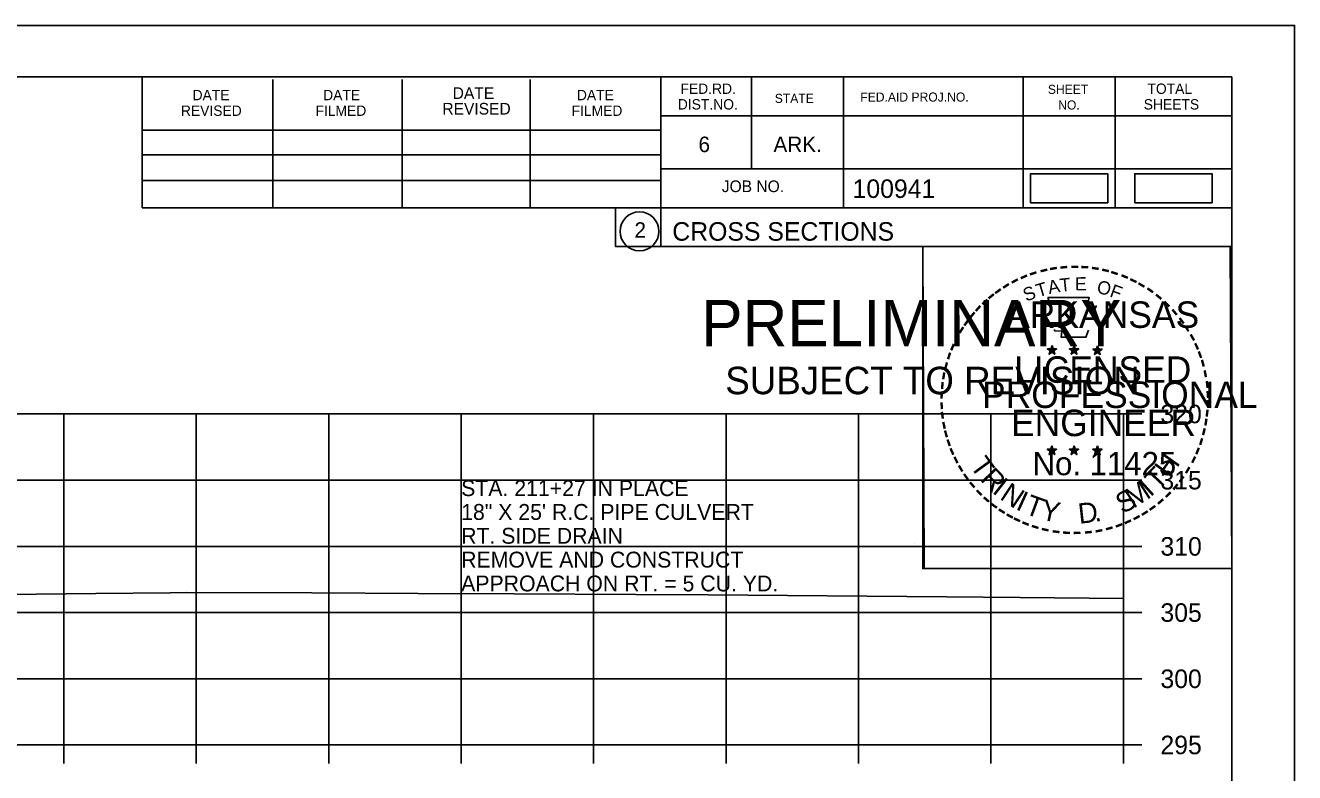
# Model space of a CAD drawing. Extents: x 1370538 to 1372872, y 376220 to 381127.
# Drawn here: x 1370775.7 to 1370871.5, y 379424.9 to 379481.3 of the extents above; entities that cross this region are included whole.
import ezdxf

# ---------------------------------------------------------------- set-up
doc = ezdxf.new("R2010")
doc.units = 0
for name, color, linetype in [('Default', 7, 'Continuous'), ('R_Border Notes', 7, 'Continuous'), ('R_Border PE', 7, 'Continuous'), ('R_Border Prem', 7, 'Continuous'), ('R_Dimension', 7, 'Continuous'), ('R_Grid', 7, 'Continuous'), ('R_No Plot', 7, 'Continuous'), ('R_Water Annot', 7, 'Continuous'), ('T_Indications', 7, 'Continuous'), ('T_Notes', 7, 'Continuous')]:
    doc.layers.add(name, color=color, linetype=linetype)

msp = doc.modelspace()

# ---------------------------------------------------------------- linework, layer by layer
at = {"layer": 'Default'}
for points in [[(1370851.6, 379467.904), (1370857.433, 379467.904), (1370857.433, 379470.09), (1370851.6, 379470.09)], [(1370859.47, 379467.904), (1370865.303, 379467.904), (1370865.303, 379470.09), (1370859.47, 379470.09)]]:
    msp.add_lwpolyline(points, close=True, dxfattribs=at)
at = {"layer": 'R_Border Notes'}
for p, q in [((1370550.607, 379477.407), (1370866.787, 379477.407)), ((1370784.527, 379467.527), (1370784.527, 379477.407)), ((1370794.387, 379467.527), (1370794.387, 379477.207)), ((1370804.147, 379467.527), (1370804.147, 379477.207)), ((1370813.827, 379467.527), (1370813.827, 379477.207)), ((1370823.687, 379477.407), (1370823.687, 379464.607)), ((1370830.527, 379477.407), (1370830.527, 379470.467)), ((1370837.467, 379477.407), (1370837.467, 379467.527)), ((1370851.047, 379477.407), (1370851.047, 379467.527)), ((1370857.987, 379477.407), (1370857.987, 379467.527)), ((1370866.787, 379271.947), (1370866.787, 379477.407)), ((1370866.787, 379474.467), (1370823.687, 379474.467)), ((1370866.787, 379474.487), (1370866.787, 379474.487)), ((1370784.527, 379473.387), (1370823.687, 379473.387)), ((1370784.527, 379471.527), (1370823.687, 379471.527)), ((1370866.787, 379470.467), (1370823.687, 379470.467)), ((1370826.647, 379470.467), (1370866.787, 379470.467)), ((1370784.527, 379467.527), (1370784.527, 379469.587)), ((1370784.527, 379469.587), (1370823.687, 379469.587)), ((1370866.787, 379467.527), (1370784.527, 379467.527)), ((1370823.687, 379464.607), (1370866.787, 379464.607))]:
    msp.add_line(p, q, dxfattribs=at)
msp.add_circle((1370822.073, 379465.743), 1.467, dxfattribs=at)
at = {"layer": 'R_Border Prem'}
for p, q in [((1370858.607, 379426.947), (1370858.607, 379451.947)), ((1370860.007, 379451.947), (1370858.607, 379451.947)), ((1370860.007, 379446.947), (1370858.607, 379446.947)), ((1370860.007, 379441.947), (1370858.607, 379441.947)), ((1370860.007, 379436.947), (1370858.607, 379436.947)), ((1370860.007, 379431.947), (1370858.607, 379431.947)), ((1370558.607, 379426.947), (1370858.607, 379426.947)), ((1370778.607, 379425.547), (1370778.607, 379426.947)), ((1370788.607, 379425.547), (1370788.607, 379426.947)), ((1370798.607, 379425.547), (1370798.607, 379426.947)), ((1370808.607, 379425.547), (1370808.607, 379426.947)), ((1370818.607, 379425.547), (1370818.607, 379426.947)), ((1370828.607, 379425.547), (1370828.607, 379426.947)), ((1370838.607, 379425.547), (1370838.607, 379426.947)), ((1370848.607, 379425.547), (1370848.607, 379426.947)), ((1370858.607, 379425.547), (1370858.607, 379426.947)), ((1370860.007, 379426.947), (1370858.607, 379426.947))]:
    msp.add_line(p, q, dxfattribs=at)
at = {"layer": 'R_Dimension'}
msp.add_lwpolyline([(1370767.559, 379438.24), (1370781.015, 379438.397), (1370786.627, 379438.44), (1370787.849, 379438.47), (1370797.339, 379438.437), (1370805.361, 379438.394), (1370812.609, 379438.367), (1370821.797, 379438.318), (1370827.261, 379438.291), (1370845.258, 379438.14), (1370850.811, 379438.084), (1370858.607, 379438.021)], dxfattribs=at)
at = {"layer": 'R_Grid'}
for p, q in [((1370558.607, 379451.947), (1370858.607, 379451.947)), ((1370778.607, 379426.947), (1370778.607, 379451.947)), ((1370788.607, 379426.947), (1370788.607, 379451.947)), ((1370798.607, 379426.947), (1370798.607, 379451.947)), ((1370808.607, 379426.947), (1370808.607, 379451.947)), ((1370818.607, 379426.947), (1370818.607, 379451.947)), ((1370828.607, 379426.947), (1370828.607, 379451.947)), ((1370838.607, 379426.947), (1370838.607, 379451.947)), ((1370848.607, 379426.947), (1370848.607, 379451.947)), ((1370858.607, 379426.947), (1370858.607, 379451.947)), ((1370558.607, 379446.947), (1370858.607, 379446.947)), ((1370558.607, 379441.947), (1370858.607, 379441.947)), ((1370558.607, 379436.947), (1370858.607, 379436.947)), ((1370558.607, 379431.947), (1370858.607, 379431.947)), ((1370558.607, 379426.947), (1370858.607, 379426.947))]:
    msp.add_line(p, q, dxfattribs=at)
at = {"layer": 'R_No Plot'}
for p, q in [((1370538.206, 379481.302), (1370871.539, 379481.302)), ((1370842.821, 379442.152), (1370842.821, 379442.152))]:
    msp.add_line(p, q, dxfattribs=at)
for points in [[(1370538.199, 379481.302), (1370871.539, 379481.302), (1370871.539, 379267.964), (1370538.199, 379267.964)], [(1370784.527, 379477.407), (1370784.527, 379467.527), (1370820.259, 379467.527), (1370820.259, 379464.607), (1370843.458, 379464.607), (1370843.458, 379440.275), (1370866.787, 379440.275), (1370866.787, 379271.947), (1370550.607, 379271.947), (1370550.607, 379477.407)], [(1370843.458, 379464.607), (1370866.666, 379464.607), (1370866.787, 379440.275), (1370843.579, 379440.275)]]:
    msp.add_lwpolyline(points, close=True, dxfattribs=at)
at = {"layer": 'T_Indications'}
for p, q in [((1370852.871, 379456.862), (1370853.22, 379456.751)), ((1370852.871, 379456.862), (1370853.124, 379456.817)), ((1370852.871, 379456.862), (1370853.108, 379456.74)), ((1370853.004, 379456.454), (1370853.22, 379456.751)), ((1370853.004, 379456.454), (1370853.13, 379456.698)), ((1370853.004, 379456.454), (1370853.218, 379456.671)), ((1370853.22, 379457.116), (1370853.179, 379456.864)), ((1370853.433, 379456.454), (1370853.218, 379456.668)), ((1370853.22, 379456.751), (1370853.22, 379457.116)), ((1370853.22, 379457.116), (1370853.269, 379456.866)), ((1370853.567, 379456.862), (1370853.22, 379456.751)), ((1370853.433, 379456.454), (1370853.22, 379456.751)), ((1370853.567, 379456.862), (1370853.281, 379456.813)), ((1370853.433, 379456.454), (1370853.296, 379456.745)), ((1370853.567, 379456.862), (1370853.363, 379456.76)), ((1370854.541, 379456.862), (1370854.89, 379456.751)), ((1370854.541, 379456.862), (1370854.794, 379456.817)), ((1370854.541, 379456.862), (1370854.778, 379456.74)), ((1370854.674, 379456.454), (1370854.89, 379456.751)), ((1370854.674, 379456.454), (1370854.8, 379456.698)), ((1370854.674, 379456.454), (1370854.888, 379456.671)), ((1370854.89, 379457.116), (1370854.849, 379456.864)), ((1370855.103, 379456.454), (1370854.888, 379456.668)), ((1370854.89, 379456.751), (1370854.89, 379457.116)), ((1370854.89, 379457.116), (1370854.939, 379456.866)), ((1370855.237, 379456.862), (1370854.89, 379456.751)), ((1370855.103, 379456.454), (1370854.89, 379456.751)), ((1370855.237, 379456.862), (1370854.951, 379456.813)), ((1370855.103, 379456.454), (1370854.966, 379456.745)), ((1370855.237, 379456.862), (1370855.033, 379456.76)), ((1370856.305, 379456.85), (1370856.654, 379456.739)), ((1370856.305, 379456.85), (1370856.558, 379456.805)), ((1370856.305, 379456.85), (1370856.542, 379456.728)), ((1370856.438, 379456.442), (1370856.654, 379456.739)), ((1370856.438, 379456.442), (1370856.564, 379456.686)), ((1370856.438, 379456.442), (1370856.652, 379456.659)), ((1370856.654, 379457.104), (1370856.613, 379456.852)), ((1370856.867, 379456.442), (1370856.652, 379456.656)), ((1370856.654, 379456.739), (1370856.654, 379457.104)), ((1370856.654, 379457.104), (1370856.703, 379456.854)), ((1370857.001, 379456.85), (1370856.654, 379456.739)), ((1370856.867, 379456.442), (1370856.654, 379456.739)), ((1370857.001, 379456.85), (1370856.715, 379456.801)), ((1370856.867, 379456.442), (1370856.73, 379456.733)), ((1370857.001, 379456.85), (1370856.797, 379456.748)), ((1370852.867, 379449.289), (1370853.216, 379449.178)), ((1370852.867, 379449.289), (1370853.12, 379449.244)), ((1370852.867, 379449.289), (1370853.104, 379449.167)), ((1370853, 379448.881), (1370853.216, 379449.178)), ((1370853, 379448.881), (1370853.126, 379449.125)), ((1370853, 379448.881), (1370853.214, 379449.098)), ((1370853.216, 379449.543), (1370853.175, 379449.291)), ((1370853.429, 379448.881), (1370853.214, 379449.095)), ((1370853.216, 379449.178), (1370853.216, 379449.543)), ((1370853.216, 379449.543), (1370853.265, 379449.293)), ((1370853.563, 379449.289), (1370853.216, 379449.178)), ((1370853.429, 379448.881), (1370853.216, 379449.178)), ((1370853.563, 379449.289), (1370853.277, 379449.24)), ((1370853.429, 379448.881), (1370853.292, 379449.172)), ((1370853.563, 379449.289), (1370853.359, 379449.187)), ((1370854.536, 379449.289), (1370854.885, 379449.178)), ((1370854.536, 379449.289), (1370854.789, 379449.244)), ((1370854.536, 379449.289), (1370854.773, 379449.167)), ((1370854.669, 379448.881), (1370854.885, 379449.178)), ((1370854.669, 379448.881), (1370854.795, 379449.125)), ((1370854.669, 379448.881), (1370854.883, 379449.098)), ((1370854.885, 379449.543), (1370854.844, 379449.291)), ((1370855.098, 379448.881), (1370854.883, 379449.095)), ((1370854.885, 379449.178), (1370854.885, 379449.543)), ((1370854.885, 379449.543), (1370854.934, 379449.293)), ((1370855.232, 379449.289), (1370854.885, 379449.178)), ((1370855.098, 379448.881), (1370854.885, 379449.178)), ((1370855.232, 379449.289), (1370854.946, 379449.24)), ((1370855.098, 379448.881), (1370854.961, 379449.172)), ((1370855.232, 379449.289), (1370855.028, 379449.187)), ((1370856.303, 379449.279), (1370856.652, 379449.168)), ((1370856.303, 379449.279), (1370856.556, 379449.234)), ((1370856.303, 379449.279), (1370856.54, 379449.157)), ((1370856.436, 379448.871), (1370856.652, 379449.168)), ((1370856.436, 379448.871), (1370856.562, 379449.115)), ((1370856.436, 379448.871), (1370856.65, 379449.088)), ((1370856.652, 379449.533), (1370856.611, 379449.281)), ((1370856.865, 379448.871), (1370856.65, 379449.085)), ((1370856.652, 379449.168), (1370856.652, 379449.533)), ((1370856.652, 379449.533), (1370856.701, 379449.283)), ((1370856.999, 379449.279), (1370856.652, 379449.168)), ((1370856.865, 379448.871), (1370856.652, 379449.168)), ((1370856.999, 379449.279), (1370856.713, 379449.23)), ((1370856.865, 379448.871), (1370856.728, 379449.162)), ((1370856.999, 379449.279), (1370856.795, 379449.177))]:
    msp.add_line(p, q, dxfattribs=at)
for points in [[(1370852.912, 379460.74), (1370853.181, 379459.913)], [(1370856.423, 379459.818), (1370856.565, 379460.102), (1370855.88, 379460.078), (1370856.028, 379460.74), (1370852.912, 379460.74)], [(1370853.404, 379458.317), (1370853.404, 379458.23), (1370853.967, 379458.211), (1370853.913, 379457.738), (1370855.783, 379457.738), (1370855.984, 379458.274)], [(1370853.22, 379457.116), (1370853.433, 379456.454), (1370852.871, 379456.862), (1370853.567, 379456.862), (1370853.004, 379456.454), (1370853.22, 379457.116)], [(1370854.89, 379457.116), (1370855.103, 379456.454), (1370854.541, 379456.862), (1370855.237, 379456.862), (1370854.674, 379456.454), (1370854.89, 379457.116)], [(1370856.654, 379457.104), (1370856.867, 379456.442), (1370856.305, 379456.85), (1370857.001, 379456.85), (1370856.438, 379456.442), (1370856.654, 379457.104)], [(1370853.216, 379449.543), (1370853.429, 379448.881), (1370852.867, 379449.289), (1370853.563, 379449.289), (1370853, 379448.881), (1370853.216, 379449.543)], [(1370854.885, 379449.543), (1370855.098, 379448.881), (1370854.536, 379449.289), (1370855.232, 379449.289), (1370854.669, 379448.881), (1370854.885, 379449.543)], [(1370856.652, 379449.533), (1370856.865, 379448.871), (1370856.303, 379449.279), (1370856.999, 379449.279), (1370856.436, 379448.871), (1370856.652, 379449.533)]]:
    msp.add_lwpolyline(points, dxfattribs=at)
for centre, radius in [((1370853.219, 379456.751), 0.172), ((1370853.219, 379456.751), 0.145), ((1370853.219, 379456.751), 0.116), ((1370853.219, 379456.751), 0.0991), ((1370853.219, 379456.751), 0.0747), ((1370853.219, 379456.751), 0.0495), ((1370853.219, 379456.751), 0.0296), ((1370854.889, 379456.751), 0.172), ((1370854.889, 379456.751), 0.145), ((1370854.889, 379456.751), 0.116), ((1370854.889, 379456.751), 0.0991), ((1370854.889, 379456.751), 0.0747), ((1370854.889, 379456.751), 0.0495), ((1370854.889, 379456.751), 0.0296), ((1370856.653, 379456.739), 0.172), ((1370856.653, 379456.739), 0.145), ((1370856.653, 379456.739), 0.116), ((1370856.653, 379456.739), 0.0991), ((1370856.653, 379456.739), 0.0747), ((1370856.653, 379456.739), 0.0495), ((1370856.653, 379456.739), 0.0296), ((1370853.215, 379449.178), 0.172), ((1370853.215, 379449.178), 0.145), ((1370853.215, 379449.178), 0.116), ((1370853.215, 379449.178), 0.0991), ((1370853.215, 379449.178), 0.0747), ((1370853.215, 379449.178), 0.0495), ((1370853.215, 379449.178), 0.0296), ((1370854.884, 379449.178), 0.172), ((1370854.884, 379449.178), 0.145), ((1370854.884, 379449.178), 0.116), ((1370854.884, 379449.178), 0.0991), ((1370854.884, 379449.178), 0.0747), ((1370854.884, 379449.178), 0.0495), ((1370854.884, 379449.178), 0.0296), ((1370856.651, 379449.168), 0.172), ((1370856.651, 379449.168), 0.145), ((1370856.651, 379449.168), 0.116), ((1370856.651, 379449.168), 0.0991), ((1370856.651, 379449.168), 0.0747), ((1370856.651, 379449.168), 0.0495), ((1370856.651, 379449.168), 0.0296)]:
    msp.add_circle(centre, radius, dxfattribs=at)

# ---------------------------------------------------------------- texts
at = {"layer": 'R_Border Notes'}
for s, height, p in [('FED.RD.', 0.7819, (1370825.167, 379476.127)), ('SHEET', 0.684, (1370852.907, 379476.127)), ('TOTAL', 0.7819, (1370860.427, 379476.127)), ('DATE', 0.7819, (1370788.327, 379475.647)), ('DATE', 0.7819, (1370798.187, 379475.647)), ('DATE', 0.8792, (1370807.967, 379475.747)), ('DATE', 0.7819, (1370817.347, 379475.647)), ('STATE', 0.684, (1370832.287, 379475.447)), ('FED.AID PROJ.NO.', 0.684, (1370838.747, 379475.547)), ('REVISED', 0.7819, (1370787.447, 379474.467)), ('FILMED', 0.7819, (1370797.607, 379474.467)), ('REVISED', 0.8792, (1370807.187, 379474.567)), ('FILMED', 0.7819, (1370816.947, 379474.467)), ('DIST.NO.', 0.7819, (1370824.967, 379474.947)), ('NO.', 0.684, (1370853.687, 379474.947)), ('SHEETS', 0.7819, (1370860.147, 379474.947)), ('6', 1.172, (1370826.527, 379471.727)), ('ARK.', 1.1723, (1370832.187, 379471.727)), ('JOB NO.', 0.8792, (1370828.287, 379468.707)), ('100941', 1.4, (1370838.162, 379468.267)), ('2', 1.172, (1370821.691, 379465.257)), ('CROSS SECTIONS', 1.4, (1370824.55, 379465.037))]:
    msp.add_text(s, height=height, rotation=360, dxfattribs=at).set_placement(p)
at = {"layer": 'R_Border PE'}
for s, p in [('320', (1370861.407, 379451.247)), ('315', (1370861.407, 379446.247)), ('310', (1370861.407, 379441.247)), ('305', (1370861.407, 379436.247)), ('300', (1370861.407, 379431.247)), ('295', (1370861.407, 379426.247))]:
    msp.add_text(s, height=1.4, dxfattribs=at).set_placement(p)
at = {"layer": 'R_Water Annot'}
for s, p in [('STA. 211+27 IN PLACE', (1370808.607, 379445.747)), ('18" X 25\' R.C. PIPE CULVERT', (1370808.607, 379443.947)), ('RT. SIDE DRAIN', (1370808.607, 379442.147)), ('REMOVE AND CONSTRUCT', (1370808.607, 379440.347)), ('APPROACH ON RT. = 5 CU. YD.', (1370808.607, 379438.547))]:
    msp.add_text(s, height=1.2, dxfattribs=at).set_placement(p)
at = {"layer": 'T_Indications'}
for s, height, rotation, p in [('-', 1.6, 24.30721, (1370851.026, 379461.598)), ('-', 1.6, 19.17608, (1370851.66, 379461.867)), ('-', 1.6, 13.63015, (1370852.41, 379462.108)), ('-', 1.6, 10.21935, (1370853.088, 379462.27)), ('-', 1.6, 5.89682, (1370853.817, 379462.38)), ('-', 1.6, 0.18623, (1370854.589, 379462.452)), ('-', 1.6, 357.74304, (1370855.312, 379462.439)), ('-', 1.6, 352.16172, (1370856.056, 379462.383)), ('-', 1.6, 347.20489, (1370856.775, 379462.269)), ('-', 1.6, 342.3362, (1370857.41, 379462.114)), ('-', 1.6, 337.85509, (1370858.145, 379461.891)), ('-', 1.6, 36.23174, (1370849.218, 379460.516)), ('-', 1.6, 34.06357, (1370849.796, 379460.911)), ('-', 1.6, 28.79182, (1370850.393, 379461.281)), ('S', 1, 21.59401, (1370851.267, 379460.418)), ('T', 1, 16.4036, (1370852.181, 379460.749)), ('A', 1, 11.21318, (1370853.007, 379461)), ('T', 1, 6.02276, (1370853.856, 379461.166)), ('E', 1, 0.83234, (1370854.961, 379461.276)), ('O', 1, 350.4515, (1370856.565, 379461.066)), ('F', 1, 340.07066, (1370857.519, 379460.838)), ('-', 1.6, 334.12109, (1370858.776, 379461.62)), ('-', 1.6, 329.64089, (1370859.355, 379461.337)), ('-', 1.6, 325.86266, (1370859.998, 379460.976)), ('-', 1.6, 42.96224, (1370848.309, 379459.721)), ('-', 1.6, 38.95066, (1370848.742, 379460.138)), ('ARKANSAS', 2, 360, (1370849.765, 379458.452)), ('-', 1.6, 320.52971, (1370860.608, 379460.55)), ('-', 1.6, 315.57859, (1370861.207, 379460.062)), ('-', 1.6, 50.61417, (1370847.458, 379458.757)), ('-', 1.6, 48.42305, (1370847.861, 379459.243)), ('-', 1.6, 309.87973, (1370861.776, 379459.512)), ('-', 1.6, 58.07063, (1370846.72, 379457.663)), ('-', 1.6, 54.23247, (1370847.045, 379458.19)), ('-', 1.6, 306.65218, (1370862.301, 379458.91)), ('-', 1.4, 303.67529, (1370862.787, 379458.342)), ('-', 1.6, 62.87135, (1370846.407, 379457.049)), ('-', 1.6, 299.66835, (1370863.106, 379457.735)), ('-', 1.6, 72.39447, (1370845.929, 379455.808)), ('-', 1.6, 67.77427, (1370846.148, 379456.438)), ('DWB', 0.01, 360, (1370853.208, 379456.746)), ('DWB', 0.01, 360, (1370854.877, 379456.746)), ('DWB', 0.01, 360, (1370856.642, 379456.735)), ('-', 1.6, 294.66279, (1370863.43, 379457.123)), ('-', 1.6, 290.57283, (1370863.687, 379456.546)), ('-', 1.6, 75.46096, (1370845.732, 379455.094)), ('LICENSED', 2, 360, (1370850.363, 379454.303)), ('-', 1.6, 285.12326, (1370863.921, 379455.966)), ('-', 1.6, 81.20126, (1370845.6, 379454.381)), ('-', 1.6, 280.54934, (1370864.121, 379455.224)), ('-', 1.6, 85.18634, (1370845.524, 379453.69)), ('PROFESSIONAL', 2, 360, (1370847.939, 379452.399)), ('-', 1.6, 276.59616, (1370864.283, 379454.456)), ('-', 1.6, 94.19588, (1370845.534, 379452.264)), ('-', 1.6, 89.06224, (1370845.499, 379452.989)), ('-', 1.6, 274.33011, (1370864.343, 379453.734)), ('-', 1.6, 269.94067, (1370864.377, 379453.102)), ('-', 1.6, 98.94793, (1370845.606, 379451.597)), ('ENGINEER', 2, 360, (1370850.126, 379450.274)), ('-', 1.6, 263.5172, (1370864.358, 379452.436)), ('-', 1.6, 101.71495, (1370845.741, 379450.864)), ('-', 1.6, 255.7626, (1370864.177, 379451.104)), ('-', 1.6, 260.99529, (1370864.287, 379451.782)), ('-', 1.6, 105.45785, (1370845.903, 379450.269)), ('-', 1.6, 109.08742, (1370846.118, 379449.638)), ('-', 1.6, 252.86809, (1370863.996, 379450.384)), ('-', 1.6, 114.06432, (1370846.372, 379449.042)), ('No. 11425', 1.757, 360, (1370851.754, 379447.323)), ('DWB', 0.01, 360, (1370853.204, 379449.173)), ('DWB', 0.01, 360, (1370854.873, 379449.174)), ('DWB', 0.01, 360, (1370856.64, 379449.164)), ('H', 1.54, 54.60883, (1370862.096, 379447.052)), ('-', 1.6, 247.88866, (1370863.773, 379449.711)), ('-', 1.6, 115.72885, (1370846.677, 379448.424)), ('-', 1.6, 120.44712, (1370847.034, 379447.838)), ('T', 1.54, 306.04056, (1370846.976, 379448.016)), ('T', 1.54, 46.64442, (1370861.207, 379446.109)), ('-', 1.6, 239.07125, (1370863.117, 379448.33)), ('-', 1.6, 244.61971, (1370863.511, 379449.082)), ('-', 1.6, 125.89344, (1370847.437, 379447.277)), ('R', 1.54, 314.00497, (1370847.739, 379446.969)), ('I', 1.54, 321.96938, (1370848.639, 379446.037)), ('I', 1.54, 42.11359, (1370860.645, 379445.631)), ('-', 1.6, 233.84524, (1370862.715, 379447.677)), ('-', 1.6, 130.71812, (1370847.899, 379446.725)), ('-', 1.6, 134.22381, (1370848.416, 379446.18)), ('N', 1.54, 326.50021, (1370849.206, 379445.565)), ('I', 1.54, 335.36034, (1370850.414, 379444.779)), ('S', 1.54, 26.9312, (1370858.522, 379444.378)), ('M', 1.54, 32.65632, (1370859.361, 379444.784)), ('-', 1.6, 225.76533, (1370861.806, 379446.547)), ('-', 1.6, 231.25377, (1370862.285, 379447.111)), ('-', 1.6, 138.93382, (1370848.941, 379445.716)), ('-', 1.6, 144.64634, (1370849.497, 379445.31)), ('T', 1.54, 339.89117, (1370851.075, 379444.452)), ('Y', 1.54, 347.85558, (1370852.292, 379444.006)), ('D', 1.54, 6.39691, (1370855.277, 379443.648)), ('-', 1.6, 221.08509, (1370861.284, 379446.038)), ('-', 1.6, 148.08978, (1370850.058, 379444.939)), ('-', 1.6, 151.57039, (1370850.637, 379444.614)), ('-', 1.6, 154.60019, (1370851.159, 379444.367)), ('-', 1.6, 207.35684, (1370859.643, 379444.833)), ('-', 1.6, 212.24909, (1370860.201, 379445.179)), ('-', 1.6, 215.73633, (1370860.735, 379445.566)), ('-', 1.6, 158.56121, (1370851.783, 379444.113)), ('-', 1.6, 162.79826, (1370852.47, 379443.9)), ('-', 1.6, 167.55551, (1370853.185, 379443.736)), ('-', 1.6, 191.28576, (1370856.994, 379443.8)), ('.', 1.54, 13.76417, (1370856.469, 379443.775)), ('-', 1.6, 195.47429, (1370857.723, 379443.999)), ('-', 1.6, 200.71842, (1370858.4, 379444.241)), ('-', 1.6, 204.25161, (1370859.019, 379444.514)), ('-', 1.6, 173.11546, (1370853.957, 379443.626)), ('-', 1.6, 176.51827, (1370854.705, 379443.573)), ('-', 1.6, 181.59176, (1370855.449, 379443.592)), ('-', 1.6, 185.81666, (1370856.258, 379443.668))]:
    msp.add_text(s, height=height, rotation=rotation, dxfattribs=at).set_placement(p)
at = {"layer": 'T_Notes'}
for s, height, p in [('PRELIMINARY', 3.5, (1370826.738, 379457.07)), ('DWB', 0.01, (1370827.484, 379458.919)), ('SUBJECT TO REVISION', 2.07511, (1370828.547, 379453.441))]:
    msp.add_text(s, height=height, rotation=360, dxfattribs=at).set_placement(p)

doc.saveas('drawing.dxf')
